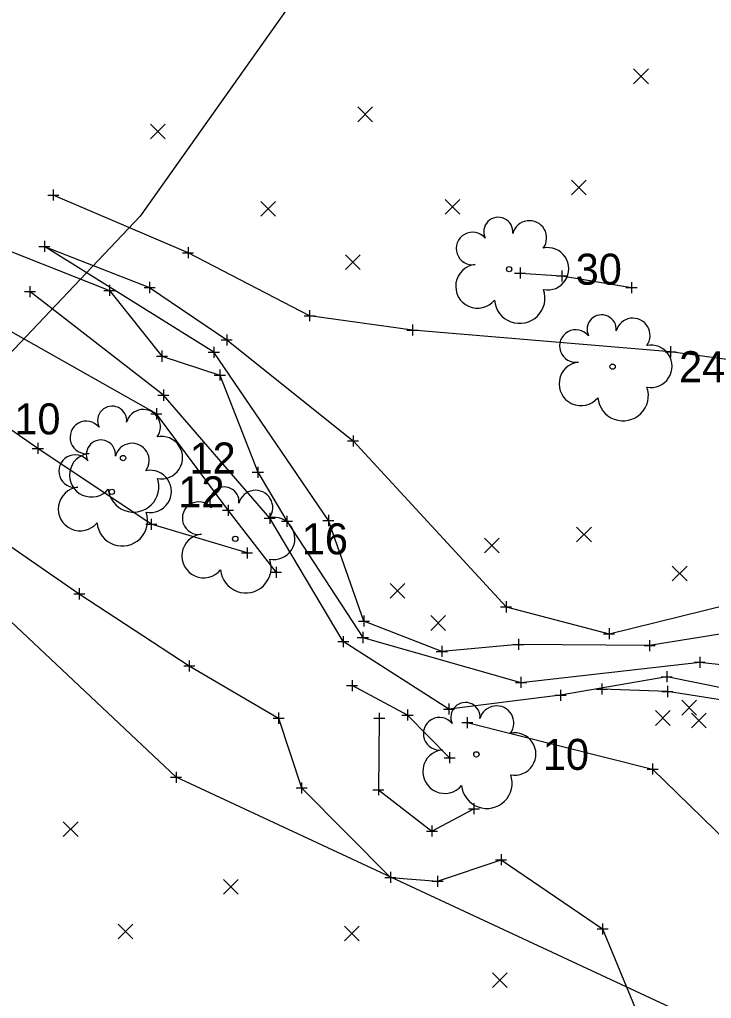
# Model space of a CAD drawing. Extents: x 2184635 to 2185378, y 369880 to 370486.
# Drawn here: x 2184775.4 to 2184837.8, y 370090.6 to 370179 of the extents above; entities that cross this region are included whole.
import ezdxf

# ---------------------------------------------------------------- set-up
doc = ezdxf.new("R2010")
doc.units = 0
for name, color, linetype in [('_CIVIL_CONSTRUCTION', 7, 'Continuous'), ('DR_X_Ditch', 7, 'Continuous'), ('GE_X_Alignment', 7, 'Continuous'), ('RW_X_CL', 7, 'Continuous'), ('SV_X_Break_Lines', 7, 'Continuous'), ('SV_X_Terrain_Boundary', 7, 'Continuous'), ('SV_X_Top_of_Bank', 7, 'Continuous'), ('VG_X_Text', 7, 'Continuous'), ('VG_X_Tree_Line_Lt', 7, 'Continuous')]:
    doc.layers.add(name, color=color, linetype=linetype)

msp = doc.modelspace()

# ---------------------------------------------------------------- linework, layer by layer
at = {"layer": '_CIVIL_CONSTRUCTION'}
for p, q in [((2184830.762, 370173.227), (2184832.095, 370174.562)), ((2184830.762, 370174.562), (2184832.095, 370173.227)), ((2184805.871, 370169.792), (2184807.204, 370171.127)), ((2184805.871, 370171.127), (2184807.204, 370169.792)), ((2184787.164, 370168.241), (2184788.498, 370169.576)), ((2184787.164, 370169.576), (2184788.498, 370168.241)), ((2184825.157, 370163.182), (2184826.491, 370164.517)), ((2184825.157, 370164.517), (2184826.491, 370163.182)), ((2184813.76, 370161.432), (2184815.094, 370162.767)), ((2184813.76, 370162.767), (2184815.094, 370161.432)), ((2184797.117, 370161.261), (2184798.451, 370162.596)), ((2184797.117, 370162.596), (2184798.451, 370161.261)), ((2184804.752, 370156.446), (2184806.086, 370157.781)), ((2184804.752, 370157.781), (2184806.086, 370156.446)), ((2184825.617, 370131.843), (2184826.95, 370133.178)), ((2184825.617, 370133.178), (2184826.95, 370131.843)), ((2184817.3, 370130.854), (2184818.633, 370132.189)), ((2184817.3, 370132.189), (2184818.633, 370130.854)), ((2184834.25, 370128.327), (2184835.584, 370129.662)), ((2184834.25, 370129.662), (2184835.584, 370128.327)), ((2184808.791, 370126.763), (2184810.124, 370128.097)), ((2184808.791, 370128.097), (2184810.124, 370126.763)), ((2184812.463, 370123.858), (2184813.797, 370125.193)), ((2184812.463, 370125.193), (2184813.797, 370123.858)), ((2184835.113, 370116.21), (2184836.446, 370117.545)), ((2184835.113, 370117.545), (2184836.446, 370116.21)), ((2184832.731, 370115.279), (2184834.064, 370116.613)), ((2184832.731, 370116.613), (2184834.064, 370115.279)), ((2184835.987, 370115.059), (2184837.321, 370116.394)), ((2184835.987, 370116.394), (2184837.321, 370115.059)), ((2184779.301, 370105.241), (2184780.634, 370106.576)), ((2184779.301, 370106.576), (2184780.634, 370105.241)), ((2184793.756, 370100.042), (2184795.089, 370101.377)), ((2184793.756, 370101.377), (2184795.089, 370100.042)), ((2184784.25, 370095.992), (2184785.584, 370097.327)), ((2184784.25, 370097.327), (2184785.584, 370095.992)), ((2184804.672, 370095.812), (2184806.005, 370097.146)), ((2184804.672, 370097.146), (2184806.005, 370095.812)), ((2184818.025, 370091.596), (2184819.358, 370092.931)), ((2184818.025, 370092.931), (2184819.358, 370091.596))]:
    msp.add_line(p, q, dxfattribs=at)
at = {"layer": 'DR_X_Ditch'}
msp.add_lwpolyline([(2184772.746, 370158.792), (2184783.456, 370154.562), (2184788.197, 370148.62), (2184793.425, 370146.92), (2184796.855, 370138.137), (2184799.486, 370133.714), (2184806.332, 370123.218), (2184820.592, 370119.162), (2184836.73, 370120.979), (2184847.133, 370119.834), (2184851.315, 370116.623), (2184858.24, 370123.687), (2184860.323, 370138.18), (2184863.22, 370162.438), (2184862.5, 370178.198), (2184848.599, 370182.845), (2184832.556, 370191.984), (2184837.703, 370200.441), (2184846.188, 370203.361)], dxfattribs=at)
at = {"layer": 'GE_X_Alignment'}
for centre in [(2184819.536, 370156.475), (2184828.864, 370147.673), (2184784.691, 370139.424), (2184783.677, 370136.369), (2184794.822, 370132.126), (2184816.572, 370112.662)]:
    msp.add_circle(centre, 0.24, dxfattribs=at)
for centre, radius, start, end in [((2184818.553, 370159.843), 1.317, 354.0047, 205.97412), ((2184821.362, 370159.304), 1.553, 323.82996, 165.0376), ((2184816.227, 370158.339), 1.471, 39.06254, 279.54124), ((2184822.997, 370156.511), 1.915, 259.14531, 101.45961), ((2184816.683, 370154.926), 1.974, 96.17219, 320.57371), ((2184820.483, 370153.87), 2.284, 184.94757, 19.45715), ((2184827.881, 370151.041), 1.317, 354.0047, 205.97412), ((2184830.691, 370150.502), 1.553, 323.82996, 165.0376), ((2184825.555, 370149.537), 1.471, 39.06254, 279.54124), ((2184832.325, 370147.709), 1.915, 259.14531, 101.45961), ((2184826.011, 370146.125), 1.974, 96.17219, 320.57371), ((2184829.811, 370145.068), 2.284, 184.94757, 19.45715), ((2184783.707, 370142.791), 1.317, 354.0047, 205.97412), ((2184786.517, 370142.253), 1.553, 323.82996, 165.0376), ((2184781.381, 370141.288), 1.471, 39.06254, 279.54124), ((2184782.693, 370139.737), 1.317, 354.0047, 205.97412), ((2184785.503, 370139.198), 1.553, 323.82996, 165.0376), ((2184788.151, 370139.46), 1.915, 259.14531, 101.45961), ((2184780.367, 370138.233), 1.471, 39.06254, 279.54124), ((2184781.837, 370137.875), 1.974, 96.17219, 320.57371), ((2184787.137, 370136.405), 1.915, 259.14531, 101.45961), ((2184785.637, 370136.818), 2.284, 184.94757, 19.45715), ((2184780.823, 370134.82), 1.974, 96.17219, 320.57371), ((2184793.839, 370135.494), 1.317, 354.0047, 205.97412), ((2184796.648, 370134.955), 1.553, 323.82996, 165.0376), ((2184791.513, 370133.99), 1.471, 39.06254, 279.54124), ((2184784.623, 370133.764), 2.284, 184.94757, 19.45715), ((2184798.283, 370132.162), 1.915, 259.14531, 101.45961), ((2184791.969, 370130.578), 1.974, 96.17219, 320.57371), ((2184795.769, 370129.521), 2.284, 184.94757, 19.45715), ((2184815.588, 370116.03), 1.317, 354.0047, 205.97412), ((2184818.398, 370115.491), 1.553, 323.82996, 165.0376), ((2184813.262, 370114.526), 1.471, 39.06254, 279.54124), ((2184820.032, 370112.698), 1.915, 259.14531, 101.45961), ((2184813.718, 370111.113), 1.974, 96.17219, 320.57371), ((2184817.518, 370110.057), 2.284, 184.94757, 19.45715)]:
    msp.add_arc(centre, radius, start, end, dxfattribs=at)
at = {"layer": 'RW_X_CL'}
for p, q in [((2184778.39, 370163.674), (2184778.39, 370162.674)), ((2184777.89, 370163.174), (2184778.89, 370163.174)), ((2184778.39, 370163.174), (2184778.39, 370163.174)), ((2184777.09, 370158.53), (2184778.09, 370158.53)), ((2184777.59, 370159.03), (2184777.59, 370158.03)), ((2184777.59, 370158.53), (2184777.59, 370158.53)), ((2184790.555, 370158.466), (2184790.555, 370157.466)), ((2184790.055, 370157.966), (2184791.055, 370157.966)), ((2184790.555, 370157.966), (2184790.555, 370157.966)), ((2184820.513, 370156.624), (2184820.513, 370155.624)), ((2184820.013, 370156.124), (2184821.013, 370156.124)), ((2184820.513, 370156.124), (2184820.513, 370156.124)), ((2184823.801, 370155.87), (2184824.801, 370155.87)), ((2184824.301, 370156.37), (2184824.301, 370155.37)), ((2184824.301, 370155.87), (2184824.301, 370155.87)), ((2184776.293, 370154.953), (2184776.293, 370153.953)), ((2184783.456, 370155.062), (2184783.456, 370154.062)), ((2184786.587, 370154.826), (2184787.587, 370154.826)), ((2184787.087, 370155.326), (2184787.087, 370154.326)), ((2184787.087, 370154.826), (2184787.087, 370154.826)), ((2184830.075, 370154.817), (2184831.075, 370154.817)), ((2184830.575, 370155.317), (2184830.575, 370154.317)), ((2184830.575, 370154.817), (2184830.575, 370154.817)), ((2184775.793, 370154.453), (2184776.793, 370154.453)), ((2184776.293, 370154.453), (2184776.293, 370154.453)), ((2184782.956, 370154.562), (2184783.956, 370154.562)), ((2184783.456, 370154.562), (2184783.456, 370154.562)), ((2184801.027, 370152.27), (2184802.027, 370152.27)), ((2184801.527, 370152.77), (2184801.527, 370151.77)), ((2184801.527, 370152.27), (2184801.527, 370152.27)), ((2184810.81, 370151.477), (2184810.81, 370150.477)), ((2184794.052, 370150.585), (2184794.052, 370149.585)), ((2184810.31, 370150.977), (2184811.31, 370150.977)), ((2184810.81, 370150.977), (2184810.81, 370150.977)), ((2184792.884, 370149.472), (2184792.884, 370148.472)), ((2184793.552, 370150.085), (2184794.552, 370150.085)), ((2184794.052, 370150.085), (2184794.052, 370150.085)), ((2184834.103, 370149.52), (2184834.103, 370148.52)), ((2184787.697, 370148.62), (2184788.697, 370148.62)), ((2184788.197, 370149.12), (2184788.197, 370148.12)), ((2184788.197, 370148.62), (2184788.197, 370148.62)), ((2184792.384, 370148.972), (2184793.384, 370148.972)), ((2184792.884, 370148.972), (2184792.884, 370148.972)), ((2184833.603, 370149.02), (2184834.603, 370149.02)), ((2184834.103, 370149.02), (2184834.103, 370149.02)), ((2184792.925, 370146.92), (2184793.925, 370146.92)), ((2184793.425, 370147.42), (2184793.425, 370146.42)), ((2184793.425, 370146.92), (2184793.425, 370146.92)), ((2184787.836, 370145.101), (2184788.836, 370145.101)), ((2184788.336, 370145.601), (2184788.336, 370144.601)), ((2184788.336, 370145.101), (2184788.336, 370145.101)), ((2184787.199, 370143.413), (2184788.199, 370143.413)), ((2184787.699, 370143.913), (2184787.699, 370142.913)), ((2184787.699, 370143.413), (2184787.699, 370143.413)), ((2184805.442, 370141.466), (2184805.442, 370140.466)), ((2184777, 370140.792), (2184777, 370139.792)), ((2184804.942, 370140.966), (2184805.942, 370140.966)), ((2184805.442, 370140.966), (2184805.442, 370140.966)), ((2184776.5, 370140.292), (2184777.5, 370140.292)), ((2184777, 370140.292), (2184777, 370140.292)), ((2184796.355, 370138.137), (2184797.355, 370138.137)), ((2184796.855, 370138.637), (2184796.855, 370137.637)), ((2184796.855, 370138.137), (2184796.855, 370138.137)), ((2184793.666, 370134.708), (2184794.666, 370134.708)), ((2184794.166, 370135.208), (2184794.166, 370134.208)), ((2184794.166, 370134.708), (2184794.166, 370134.708)), ((2184797.93, 370134.489), (2184797.93, 370133.489)), ((2184787.235, 370133.937), (2184787.235, 370132.937)), ((2184797.43, 370133.989), (2184798.43, 370133.989)), ((2184797.93, 370133.989), (2184797.93, 370133.989)), ((2184798.986, 370133.714), (2184799.986, 370133.714)), ((2184799.486, 370134.214), (2184799.486, 370133.214)), ((2184799.486, 370133.714), (2184799.486, 370133.714)), ((2184802.718, 370133.78), (2184803.718, 370133.78)), ((2184803.218, 370134.28), (2184803.218, 370133.28)), ((2184803.218, 370133.78), (2184803.218, 370133.78)), ((2184786.735, 370133.437), (2184787.735, 370133.437)), ((2184787.235, 370133.437), (2184787.235, 370133.437)), ((2184795.387, 370130.85), (2184796.387, 370130.85)), ((2184795.887, 370131.35), (2184795.887, 370130.35)), ((2184795.887, 370130.85), (2184795.887, 370130.85)), ((2184797.996, 370129.104), (2184798.996, 370129.104)), ((2184798.496, 370129.604), (2184798.496, 370128.604)), ((2184798.496, 370129.104), (2184798.496, 370129.104)), ((2184780.746, 370127.657), (2184780.746, 370126.657)), ((2184780.246, 370127.157), (2184781.246, 370127.157)), ((2184780.746, 370127.157), (2184780.746, 370127.157)), ((2184819.256, 370126.484), (2184819.256, 370125.484)), ((2184818.756, 370125.984), (2184819.756, 370125.984)), ((2184819.256, 370125.984), (2184819.256, 370125.984)), ((2184805.931, 370124.703), (2184806.931, 370124.703)), ((2184806.431, 370125.203), (2184806.431, 370124.203)), ((2184806.431, 370124.703), (2184806.431, 370124.703)), ((2184828.544, 370124.052), (2184828.544, 370123.052)), ((2184804.566, 370123.341), (2184804.566, 370122.341)), ((2184805.832, 370123.218), (2184806.832, 370123.218)), ((2184806.332, 370123.718), (2184806.332, 370122.718)), ((2184806.332, 370123.218), (2184806.332, 370123.218)), ((2184820.37, 370123.093), (2184820.37, 370122.093)), ((2184828.044, 370123.552), (2184829.044, 370123.552)), ((2184828.544, 370123.552), (2184828.544, 370123.552)), ((2184832.207, 370122.987), (2184832.207, 370121.987)), ((2184804.066, 370122.841), (2184805.066, 370122.841)), ((2184804.566, 370122.841), (2184804.566, 370122.841)), ((2184813.455, 370122.457), (2184813.455, 370121.457)), ((2184819.87, 370122.593), (2184820.87, 370122.593)), ((2184820.37, 370122.593), (2184820.37, 370122.593)), ((2184831.707, 370122.487), (2184832.707, 370122.487)), ((2184832.207, 370122.487), (2184832.207, 370122.487)), ((2184790.672, 370121.145), (2184790.672, 370120.145)), ((2184812.955, 370121.957), (2184813.955, 370121.957)), ((2184813.455, 370121.957), (2184813.455, 370121.957)), ((2184836.73, 370121.479), (2184836.73, 370120.479)), ((2184790.172, 370120.645), (2184791.172, 370120.645)), ((2184790.672, 370120.645), (2184790.672, 370120.645)), ((2184836.23, 370120.979), (2184837.23, 370120.979)), ((2184836.73, 370120.979), (2184836.73, 370120.979)), ((2184805.362, 370119.371), (2184805.362, 370118.371)), ((2184820.592, 370119.662), (2184820.592, 370118.662)), ((2184833.254, 370119.669), (2184834.254, 370119.669)), ((2184833.754, 370120.169), (2184833.754, 370119.169)), ((2184833.754, 370119.669), (2184833.754, 370119.669)), ((2184804.862, 370118.871), (2184805.862, 370118.871)), ((2184805.362, 370118.871), (2184805.362, 370118.871)), ((2184820.092, 370119.162), (2184821.092, 370119.162)), ((2184820.592, 370119.162), (2184820.592, 370119.162)), ((2184824.168, 370118.501), (2184824.168, 370117.501)), ((2184827.393, 370118.566), (2184828.393, 370118.566)), ((2184827.893, 370119.066), (2184827.893, 370118.066)), ((2184827.893, 370118.566), (2184827.893, 370118.566)), ((2184833.817, 370118.838), (2184833.817, 370117.838)), ((2184823.668, 370118.001), (2184824.668, 370118.001)), ((2184824.168, 370118.001), (2184824.168, 370118.001)), ((2184833.317, 370118.338), (2184834.317, 370118.338)), ((2184833.817, 370118.338), (2184833.817, 370118.338)), ((2184810.36, 370116.717), (2184810.36, 370115.717)), ((2184813.596, 370116.756), (2184814.596, 370116.756)), ((2184814.096, 370117.256), (2184814.096, 370116.256)), ((2184814.096, 370116.756), (2184814.096, 370116.756)), ((2184798.232, 370115.934), (2184799.232, 370115.934)), ((2184798.732, 370116.434), (2184798.732, 370115.434)), ((2184798.732, 370115.934), (2184798.732, 370115.934)), ((2184807.316, 370115.918), (2184808.316, 370115.918)), ((2184807.816, 370116.418), (2184807.816, 370115.418)), ((2184807.816, 370115.918), (2184807.816, 370115.918)), ((2184809.86, 370116.217), (2184810.86, 370116.217)), ((2184810.36, 370116.217), (2184810.36, 370116.217)), ((2184815.75, 370116.032), (2184815.75, 370115.032)), ((2184815.25, 370115.532), (2184816.25, 370115.532)), ((2184815.75, 370115.532), (2184815.75, 370115.532)), ((2184813.658, 370112.356), (2184814.658, 370112.356)), ((2184814.158, 370112.856), (2184814.158, 370111.856)), ((2184814.158, 370112.356), (2184814.158, 370112.356)), ((2184832.476, 370111.834), (2184832.476, 370110.834)), ((2184788.976, 370110.598), (2184789.976, 370110.598)), ((2184789.476, 370111.098), (2184789.476, 370110.098)), ((2184789.476, 370110.598), (2184789.476, 370110.598)), ((2184831.976, 370111.334), (2184832.976, 370111.334)), ((2184832.476, 370111.334), (2184832.476, 370111.334)), ((2184800.3, 370109.628), (2184801.3, 370109.628)), ((2184800.8, 370110.128), (2184800.8, 370109.128)), ((2184800.8, 370109.628), (2184800.8, 370109.628)), ((2184807.732, 370109.967), (2184807.732, 370108.967)), ((2184807.232, 370109.467), (2184808.232, 370109.467)), ((2184807.732, 370109.467), (2184807.732, 370109.467)), ((2184816.352, 370108.259), (2184816.352, 370107.259)), ((2184815.852, 370107.759), (2184816.852, 370107.759)), ((2184816.352, 370107.759), (2184816.352, 370107.759)), ((2184812.56, 370106.24), (2184812.56, 370105.24)), ((2184812.06, 370105.74), (2184813.06, 370105.74)), ((2184812.56, 370105.74), (2184812.56, 370105.74)), ((2184818.797, 370103.654), (2184818.797, 370102.654)), ((2184818.297, 370103.154), (2184819.297, 370103.154)), ((2184818.797, 370103.154), (2184818.797, 370103.154)), ((2184808.818, 370102.051), (2184808.818, 370101.051)), ((2184813.069, 370101.699), (2184813.069, 370100.699)), ((2184808.318, 370101.551), (2184809.318, 370101.551)), ((2184808.818, 370101.551), (2184808.818, 370101.551)), ((2184812.569, 370101.199), (2184813.569, 370101.199)), ((2184813.069, 370101.199), (2184813.069, 370101.199)), ((2184827.963, 370097.405), (2184827.963, 370096.405)), ((2184827.463, 370096.905), (2184828.463, 370096.905)), ((2184827.963, 370096.905), (2184827.963, 370096.905))]:
    msp.add_line(p, q, dxfattribs=at)
at = {"layer": 'SV_X_Break_Lines'}
for points in [[(2184847.446, 370201.078), (2184834.811, 370193.51), (2184845.709, 370185.722), (2184859.639, 370184.834), (2184862.388, 370180.309), (2184865.693, 370171.126), (2184865.101, 370155.292), (2184863.901, 370143.074), (2184860.23, 370123.219), (2184851.862, 370116.242), (2184844.781, 370117.425), (2184833.754, 370119.669), (2184824.168, 370118.001), (2184814.096, 370116.756), (2184804.566, 370122.841), (2184797.93, 370133.989), (2184788.336, 370145.101), (2184776.293, 370154.453)], [(2184846.036, 370147.383), (2184834.103, 370149.02), (2184810.81, 370150.977), (2184801.527, 370152.27), (2184790.555, 370157.966), (2184778.39, 370163.174)], [(2184847.684, 370125.007), (2184832.207, 370122.487), (2184820.37, 370122.593), (2184813.455, 370121.957), (2184806.431, 370124.703), (2184803.218, 370133.78), (2184792.884, 370148.972), (2184777.59, 370158.53), (2184787.087, 370154.826), (2184794.052, 370150.085), (2184805.442, 370140.966), (2184819.256, 370125.984), (2184828.544, 370123.552), (2184841.621, 370126.777)], [(2184820.513, 370156.124), (2184824.301, 370155.87), (2184830.575, 370154.817)], [(2184795.887, 370130.85), (2184787.235, 370133.437), (2184777, 370140.292), (2184773.621, 370142.642), (2184765.679, 370146.296)], [(2184814.158, 370112.356), (2184810.36, 370116.217), (2184805.362, 370118.871)], [(2184807.816, 370115.918), (2184807.732, 370109.467), (2184812.56, 370105.74), (2184816.352, 370107.759)], [(2184815.75, 370115.532), (2184832.476, 370111.334), (2184839.229, 370104.736), (2184843.697, 370093.937)]]:
    msp.add_lwpolyline(points, dxfattribs=at)
at = {"layer": 'SV_X_Terrain_Boundary'}
msp.add_lwpolyline([(2185048.788, 370280.746), (2184981.838, 370244.628), (2184966.756, 370227.412), (2184901.88, 370166.351), (2184859.946, 370200.015), (2184846.285, 370205.144), (2184825.044, 370216.074), (2184786.251, 370161.278), (2184768.884, 370142.96), (2184755.889, 370127.052), (2184768.662, 370083.987), (2184723.55, 370028.868), (2184709.399, 370017.08), (2184650.834, 369961.553), (2184636.069, 369950.037)], dxfattribs=at)
at = {"layer": 'SV_X_Top_of_Bank'}
for points in [[(2184798.496, 370129.104), (2184794.166, 370134.708), (2184787.699, 370143.413), (2184773.141, 370151.647)], [(2184762.675, 370135.815), (2184769.367, 370135.031), (2184780.746, 370127.157), (2184790.672, 370120.645), (2184798.732, 370115.934), (2184800.8, 370109.628), (2184808.818, 370101.551), (2184813.069, 370101.199), (2184818.797, 370103.154), (2184827.963, 370096.905), (2184832.005, 370087.065), (2184833.511, 370084.127)], [(2184848.656, 370114.257), (2184840.308, 370117.304), (2184833.817, 370118.338), (2184827.893, 370118.566)]]:
    msp.add_lwpolyline(points, dxfattribs=at)
at = {"layer": 'VG_X_Tree_Line_Lt'}
msp.add_lwpolyline([(2185010.677, 370261.152), (2185009.496, 370230.83), (2184994.447, 370214.873), (2184919.447, 370148.63), (2184883.31, 370122.364), (2184845.078, 370084.673), (2184789.476, 370110.598), (2184762.675, 370135.815)], dxfattribs=at)

# ---------------------------------------------------------------- texts
at = {"layer": 'VG_X_Text'}
for s, p in [('30', (2184825.536, 370155.075)), ('24', (2184834.864, 370146.273)), ('10', (2184774.885, 370141.56)), ('12', (2184790.691, 370138.024)), ('12', (2184789.677, 370134.969)), ('16', (2184800.822, 370130.726)), ('10', (2184822.572, 370111.262))]:
    msp.add_text(s, height=2.8, dxfattribs=at).set_placement(p)

doc.saveas('drawing.dxf')
